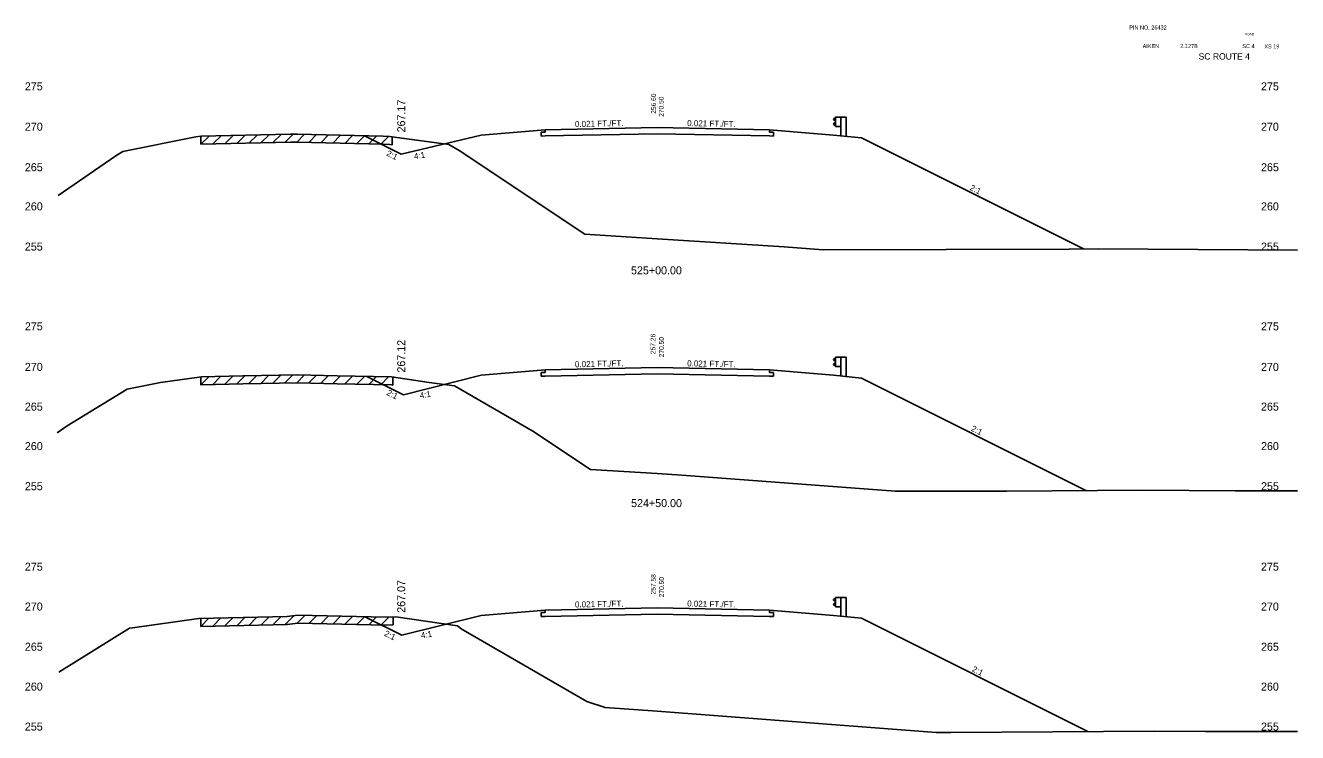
# Model space of a CAD drawing. Extents: x 883 to 1160, y 1002 to 4323.
# Drawn here: x 1001 to 1160, y 3084.9 to 3173.2 of the extents above; entities that cross this region are included whole.
import ezdxf

# ---------------------------------------------------------------- set-up
doc = ezdxf.new("R2010")
doc.units = 0
for name, color, linetype in [('Level 1', 7, 'Continuous'), ('Level 10', 7, 'Continuous'), ('Level 11', 7, 'Continuous'), ('Level 12', 7, 'Continuous'), ('Level 24', 7, 'Continuous'), ('Level 3', 7, 'Continuous'), ('Level 32', 7, 'Continuous'), ('Level 33', 7, 'Continuous'), ('Level 59', 7, 'Continuous'), ('Level 6', 7, 'Continuous'), ('Level 60', 7, 'Continuous'), ('Level 61', 7, 'Continuous'), ('Level 7', 7, 'Continuous')]:
    doc.layers.add(name, color=color, linetype=linetype)

msp = doc.modelspace()

# ---------------------------------------------------------------- linework, layer by layer
at = {"layer": 'Level 11'}
for p, q in [((1066, 3160.21), (1066, 3159.91)), ((1094, 3159.91), (1094, 3160.21)), ((1066, 3159.91), (1065.5, 3159.9)), ((1065.5, 3159.9), (1065.5, 3159.42)), ((1065.5, 3159.42), (1066, 3159.43)), ((1094.5, 3159.9), (1094, 3159.91)), ((1094, 3159.43), (1094.5, 3159.42)), ((1094.5, 3159.42), (1094.5, 3159.9)), ((1066, 3129.91), (1065.5, 3129.9)), ((1065.5, 3129.9), (1065.5, 3129.42)), ((1066, 3130.21), (1066, 3129.91)), ((1094, 3129.91), (1094, 3130.21)), ((1094.5, 3129.9), (1094, 3129.91)), ((1094.5, 3129.42), (1094.5, 3129.9)), ((1065.5, 3129.42), (1066, 3129.43)), ((1094, 3129.43), (1094.5, 3129.42)), ((1066, 3099.91), (1065.5, 3099.9)), ((1065.5, 3099.9), (1065.5, 3099.42)), ((1066, 3100.21), (1066, 3099.91)), ((1094, 3099.91), (1094, 3100.21)), ((1094.5, 3099.9), (1094, 3099.91)), ((1094.5, 3099.42), (1094.5, 3099.9)), ((1065.5, 3099.42), (1066, 3099.43)), ((1094, 3099.43), (1094.5, 3099.42))]:
    msp.add_line(p, q, dxfattribs=at)
at = {"layer": 'Level 12'}
for p, q in [((1080, 3159.72), (1066, 3159.43)), ((1094, 3159.43), (1080, 3159.72)), ((1080, 3129.72), (1066, 3129.43)), ((1094, 3129.43), (1080, 3129.72)), ((1080, 3099.72), (1066, 3099.43)), ((1094, 3099.43), (1080, 3099.72))]:
    msp.add_line(p, q, dxfattribs=at)
at = {"layer": 'Level 24'}
for p, q in [((1102.27, 3161.72), (1102, 3161.52)), ((1102.27, 3160.63), (1102.27, 3161.79)), ((1102.27, 3161.79), (1102.94, 3161.79)), ((1102.94, 3161.79), (1102.94, 3159.45)), ((1102.94, 3161.79), (1103.6, 3161.79)), ((1103.6, 3161.79), (1103.6, 3159.38)), ((1102, 3161.52), (1102, 3161.47)), ((1102, 3161.47), (1102.27, 3161.27)), ((1102, 3160.95), (1102.27, 3161.15)), ((1102, 3160.9), (1102, 3160.95)), ((1102.27, 3160.7), (1102, 3160.9)), ((1102.27, 3160.63), (1102.94, 3160.63)), ((1102.27, 3131.72), (1102, 3131.52)), ((1102, 3131.52), (1102, 3131.47)), ((1102, 3131.47), (1102.27, 3131.27)), ((1102.27, 3130.63), (1102.27, 3131.79)), ((1102.27, 3131.79), (1102.94, 3131.79)), ((1102.94, 3131.79), (1102.94, 3129.45)), ((1102.94, 3131.79), (1103.6, 3131.79)), ((1103.6, 3131.79), (1103.6, 3129.38)), ((1102, 3130.95), (1102.27, 3131.15)), ((1102, 3130.9), (1102, 3130.95)), ((1102.27, 3130.7), (1102, 3130.9)), ((1102.27, 3130.63), (1102.94, 3130.63)), ((1102.27, 3101.72), (1102, 3101.52)), ((1102, 3101.52), (1102, 3101.47)), ((1102, 3101.47), (1102.27, 3101.27)), ((1102.27, 3100.63), (1102.27, 3101.79)), ((1102.27, 3101.79), (1102.94, 3101.79)), ((1102.94, 3101.79), (1102.94, 3099.45)), ((1102.94, 3101.79), (1103.6, 3101.79)), ((1103.6, 3101.79), (1103.6, 3099.38)), ((1102, 3100.95), (1102.27, 3101.15)), ((1102, 3100.9), (1102, 3100.95)), ((1102.27, 3100.7), (1102, 3100.9)), ((1102.27, 3100.63), (1102.94, 3100.63))]:
    msp.add_line(p, q, dxfattribs=at)
at = {"layer": 'Level 59'}
for p, q in [((1066, 3160.21), (1080, 3160.5)), ((1080, 3160.5), (1094, 3160.21)), ((1066, 3130.21), (1080, 3130.5)), ((1080, 3130.5), (1094, 3130.21)), ((1066, 3100.21), (1080, 3100.5)), ((1080, 3100.5), (1094, 3100.21))]:
    msp.add_line(p, q, dxfattribs=at)
at = {"layer": 'Level 6'}
for p, q in [((1058, 3159.54), (1066, 3160.21)), ((1094, 3160.21), (1102, 3159.54)), ((1102, 3159.54), (1105.5, 3159.19)), ((1058, 3129.54), (1066, 3130.21)), ((1094, 3130.21), (1102, 3129.54)), ((1102, 3129.54), (1105.5, 3129.19)), ((1058, 3099.54), (1066, 3100.21)), ((1094, 3100.21), (1102, 3099.54)), ((1102, 3099.54), (1105.5, 3099.19))]:
    msp.add_line(p, q, dxfattribs=at)
at = {"layer": 'Level 60'}
for p, q in [((1013.22, 3157.51), (1022.33, 3159.31)), ((1022.33, 3159.31), (1022.95, 3159.4)), ((1022.95, 3159.4), (1034.16, 3159.65)), ((1034.16, 3159.65), (1035, 3159.66)), ((1035, 3159.66), (1045.74, 3159.39)), ((1045.74, 3159.39), (1046.58, 3159.38)), ((1046.58, 3159.38), (1047.17, 3159.29)), ((1047.17, 3159.29), (1053.96, 3158.35)), ((1005.12, 3151.98), (1012.32, 3156.96)), ((1012.32, 3156.96), (1013.22, 3157.51)), ((1053.96, 3158.35), (1055.26, 3157.6)), ((1055.26, 3157.6), (1070.93, 3147.18)), ((1070.93, 3147.18), (1080, 3146.6)), ((1080, 3146.6), (1095.87, 3145.6)), ((1095.87, 3145.6), (1100.72, 3145.23)), ((1100.72, 3145.23), (1131.45, 3145.31)), ((1131.45, 3145.31), (1135.14, 3145.34)), ((1135.14, 3145.34), (1160, 3145.17)), ((1013.75, 3127.83), (1017.92, 3128.65)), ((1017.92, 3128.65), (1023.06, 3129.37)), ((1023.06, 3129.37), (1028.21, 3129.48)), ((1028.21, 3129.48), (1035.03, 3129.61)), ((1035.03, 3129.61), (1039.99, 3129.49)), ((1039.99, 3129.49), (1046.77, 3129.34)), ((1046.77, 3129.34), (1051.51, 3128.65)), ((1051.51, 3128.65), (1054.64, 3128.22)), ((1006.27, 3123.22), (1013.75, 3127.83)), ((1054.64, 3128.22), (1064.43, 3122.58)), ((1005.02, 3122.36), (1006.27, 3123.22)), ((1064.43, 3122.58), (1071.63, 3117.79)), ((1071.63, 3117.79), (1080, 3117.26)), ((1080, 3117.26), (1083.08, 3117.06)), ((1083.08, 3117.06), (1109.72, 3115.06)), ((1109.72, 3115.06), (1123.68, 3115.09)), ((1123.68, 3115.09), (1140.67, 3115.21)), ((1140.67, 3115.21), (1152.22, 3115.13)), ((1152.22, 3115.13), (1160, 3115.13)), ((1014.41, 3098.02), (1022.7, 3099.18)), ((1022.7, 3099.18), (1033.76, 3099.4)), ((1033.76, 3099.4), (1035.06, 3099.57)), ((1035.06, 3099.57), (1046.08, 3099.33)), ((1046.08, 3099.33), (1047.32, 3099.37)), ((1047.32, 3099.37), (1055.03, 3098.26)), ((1055.03, 3098.26), (1055.48, 3097.89)), ((1005.2, 3092.48), (1014.06, 3097.94)), ((1014.06, 3097.94), (1014.41, 3098.02)), ((1055.48, 3097.89), (1071.2, 3088.82)), ((1071.2, 3088.82), (1073.47, 3088.07)), ((1073.47, 3088.07), (1080, 3087.58)), ((1080, 3087.58), (1114.84, 3084.93)), ((1114.84, 3084.93), (1116.66, 3084.92)), ((1116.66, 3084.92), (1142.13, 3085.11)), ((1142.13, 3085.11), (1148.47, 3085.06)), ((1148.47, 3085.06), (1160, 3085.06))]:
    msp.add_line(p, q, dxfattribs=at)
at = {"layer": 'Level 61'}
for p, q in [((1023.98, 3159.42), (1022.95, 3158.4)), ((1022.95, 3159.4), (1022.95, 3158.4)), ((1022.95, 3158.4), (1034.16, 3158.65)), ((1025.48, 3159.45), (1024.45, 3158.43)), ((1026.98, 3159.49), (1025.95, 3158.46)), ((1028.48, 3159.52), (1027.45, 3158.5)), ((1029.98, 3159.55), (1028.95, 3158.53)), ((1031.48, 3159.59), (1030.45, 3158.56)), ((1032.98, 3159.62), (1031.95, 3158.6)), ((1034.48, 3159.65), (1033.45, 3158.63)), ((1034.16, 3158.65), (1035, 3158.66)), ((1035.93, 3159.64), (1034.95, 3158.66)), ((1035, 3158.66), (1045.74, 3158.39)), ((1037.43, 3159.6), (1036.45, 3158.63)), ((1038.93, 3159.56), (1037.95, 3158.59)), ((1040.43, 3159.53), (1039.45, 3158.55)), ((1041.93, 3159.49), (1040.95, 3158.51)), ((1043.43, 3159.45), (1042.45, 3158.48)), ((1044.93, 3159.41), (1043.95, 3158.44)), ((1046.43, 3159.38), (1045.45, 3158.4)), ((1046.88, 3158.33), (1046.88, 3159.33)), ((1045.74, 3158.39), (1046.58, 3158.38)), ((1046.58, 3158.38), (1046.88, 3158.33)), ((1023.99, 3129.39), (1022.95, 3128.35)), ((1022.95, 3129.35), (1022.95, 3128.35)), ((1022.95, 3128.35), (1023.06, 3128.37)), ((1023.06, 3128.37), (1028.21, 3128.48)), ((1025.47, 3129.42), (1024.45, 3128.4)), ((1026.97, 3129.45), (1025.95, 3128.43)), ((1028.47, 3129.49), (1027.45, 3128.46)), ((1028.21, 3128.48), (1035.03, 3128.61)), ((1029.97, 3129.52), (1028.95, 3128.5)), ((1031.47, 3129.54), (1030.45, 3128.52)), ((1032.97, 3129.57), (1031.95, 3128.55)), ((1034.47, 3129.6), (1033.45, 3128.58)), ((1035.93, 3129.59), (1034.95, 3128.61)), ((1035.03, 3128.61), (1039.99, 3128.49)), ((1037.43, 3129.55), (1036.45, 3128.58)), ((1038.93, 3129.52), (1037.95, 3128.54)), ((1040.43, 3129.48), (1039.45, 3128.5)), ((1039.99, 3128.49), (1046.77, 3128.34)), ((1041.93, 3129.45), (1040.95, 3128.47)), ((1043.43, 3129.41), (1042.45, 3128.43)), ((1044.93, 3129.38), (1043.95, 3128.4)), ((1046.43, 3129.35), (1045.45, 3128.37)), ((1046.77, 3128.34), (1046.94, 3128.31)), ((1046.94, 3128.31), (1046.94, 3129.31)), ((1023.97, 3099.2), (1022.95, 3098.18)), ((1022.95, 3099.18), (1022.95, 3098.18)), ((1022.95, 3098.18), (1033.76, 3098.4)), ((1025.47, 3099.23), (1024.45, 3098.21)), ((1026.97, 3099.26), (1025.95, 3098.24)), ((1028.47, 3099.29), (1027.45, 3098.27)), ((1029.97, 3099.32), (1028.95, 3098.3)), ((1031.47, 3099.35), (1030.45, 3098.33)), ((1032.97, 3099.38), (1031.95, 3098.36)), ((1034.56, 3099.51), (1033.45, 3098.39)), ((1033.76, 3098.4), (1035.06, 3098.57)), ((1035.94, 3099.56), (1034.95, 3098.56)), ((1035.06, 3098.57), (1046.08, 3098.33)), ((1037.42, 3099.52), (1036.45, 3098.54)), ((1038.92, 3099.49), (1037.95, 3098.51)), ((1040.42, 3099.46), (1039.45, 3098.48)), ((1041.92, 3099.42), (1040.95, 3098.45)), ((1043.42, 3099.39), (1042.45, 3098.41)), ((1044.92, 3099.36), (1043.95, 3098.38)), ((1046.44, 3099.34), (1045.45, 3098.35)), ((1046.08, 3098.33), (1047.01, 3098.36)), ((1047.01, 3098.36), (1047.01, 3099.36))]:
    msp.add_line(p, q, dxfattribs=at)
at = {"layer": 'Level 7'}
for p, q in [((1043.43, 3159.45), (1048, 3157.17)), ((1048, 3157.17), (1058, 3159.54)), ((1105.5, 3159.19), (1133.24, 3145.32)), ((1043.71, 3129.41), (1048.29, 3127.12)), ((1058, 3129.54), (1048.29, 3127.12)), ((1105.5, 3129.19), (1133.56, 3115.16)), ((1043.44, 3099.39), (1048.09, 3097.07)), ((1058, 3099.54), (1048.09, 3097.07)), ((1105.5, 3099.19), (1133.79, 3085.05))]:
    msp.add_line(p, q, dxfattribs=at)

# ---------------------------------------------------------------- texts
at = {"layer": 'Level 1'}
for s, height, p in [('PIN NO. 26432', 0.5, (1138.97, 3172.73)), ('AIKEN', 0.5, (1140.64, 3170.41)), (' 2.127B', 0.5, (1145.15, 3170.41)), ('SC ROUTE 4', 0.8, (1147.63, 3168.97)), ('SC 4', 0.5, (1153.09, 3170.41)), ('XS 19', 0.5, (1155.85, 3170.37)), ('525+00.00', 1, (1076.71, 3142.15)), ('524+50.00', 1, (1076.72, 3113.08))]:
    msp.add_text(s, height=height, dxfattribs=at).set_placement(p)
at = {"layer": 'Level 10'}
for s, p in [('256.60', (1079.83, 3162.2)), ('257.26', (1079.76, 3132.19)), ('257.58', (1079.8, 3102.17))]:
    msp.add_text(s, height=0.6, rotation=90, dxfattribs=at).set_placement(p)
at = {"layer": 'Level 3'}
for s, height, p in [('ROAD', 0.3, (1153.38, 3172)), (' 275', 1, (1000.6, 3165.13)), (' 275', 1, (1155.06, 3165.13)), (' 270', 1, (1000.6, 3160.09)), (' 270', 1, (1155.06, 3160.09)), (' 265', 1, (1000.6, 3155.03)), (' 265', 1, (1155.06, 3155.03)), (' 260', 1, (1000.6, 3150.14)), (' 260', 1, (1155.06, 3150.14)), (' 255', 1, (1000.6, 3145.12)), (' 255', 1, (1155.06, 3145.12)), (' 275', 1, (1000.6, 3135.16)), (' 275', 1, (1155.06, 3135.16)), (' 270', 1, (1000.6, 3130.09)), (' 270', 1, (1155.06, 3130.09)), (' 265', 1, (1000.6, 3125.13)), (' 265', 1, (1155.06, 3125.13)), (' 260', 1, (1000.6, 3120.2)), (' 260', 1, (1155.06, 3120.2)), (' 255', 1, (1000.6, 3115.19)), (' 255', 1, (1155.06, 3115.19)), (' 275', 1, (1000.6, 3105.14)), (' 275', 1, (1155.06, 3105.14)), (' 270', 1, (1000.6, 3100.16)), (' 270', 1, (1155.06, 3100.16)), (' 265', 1, (1000.6, 3095.14)), (' 265', 1, (1155.06, 3095.14)), (' 260', 1, (1000.6, 3090.16)), (' 260', 1, (1155.06, 3090.16)), (' 255', 1, (1000.6, 3085.17)), (' 255', 1, (1155.06, 3085.17))]:
    msp.add_text(s, height=height, dxfattribs=at).set_placement(p)
at = {"layer": 'Level 32'}
for s, rotation, p in [('0.021 FT./FT.', 1.1916, (1069.71, 3160.54)), ('0.021 FT./FT.', 358.8084, (1083.72, 3160.67)), ('2:1', 333.435, (1046.07, 3157.02)), ('4:1', 9.4623, (1049.66, 3156.51)), ('2:1', 333.435, (1118.97, 3152.73)), ('0.021 FT./FT.', 1.1916, (1069.71, 3130.54)), ('0.021 FT./FT.', 358.8084, (1083.72, 3130.67)), ('2:1', 333.435, (1046.1, 3127.13)), ('4:1', 9.4623, (1050.37, 3126.64)), ('2:1', 333.435, (1119.14, 3122.65)), ('0.021 FT./FT.', 1.1916, (1069.71, 3100.54)), ('0.021 FT./FT.', 358.8084, (1083.72, 3100.67)), ('2:1', 333.435, (1045.81, 3097.05)), ('4:1', 9.4623, (1050.52, 3096.67)), ('2:1', 333.435, (1119.25, 3092.6))]:
    msp.add_text(s, height=0.75, rotation=rotation, dxfattribs=at).set_placement(p)
at = {"layer": 'Level 33'}
for s, p in [('267.17', (1048.5, 3159.88)), ('267.12', (1048.5, 3129.88)), ('267.07', (1048.5, 3099.88))]:
    msp.add_text(s, height=1, rotation=90, dxfattribs=at).set_placement(p)
at = {"layer": 'Level 59'}
for p in [(1080.79, 3161.59), (1080.82, 3131.56), (1080.82, 3101.59)]:
    msp.add_text(' 270.50', height=0.6, rotation=90, dxfattribs=at).set_placement(p)

doc.saveas('drawing.dxf')
